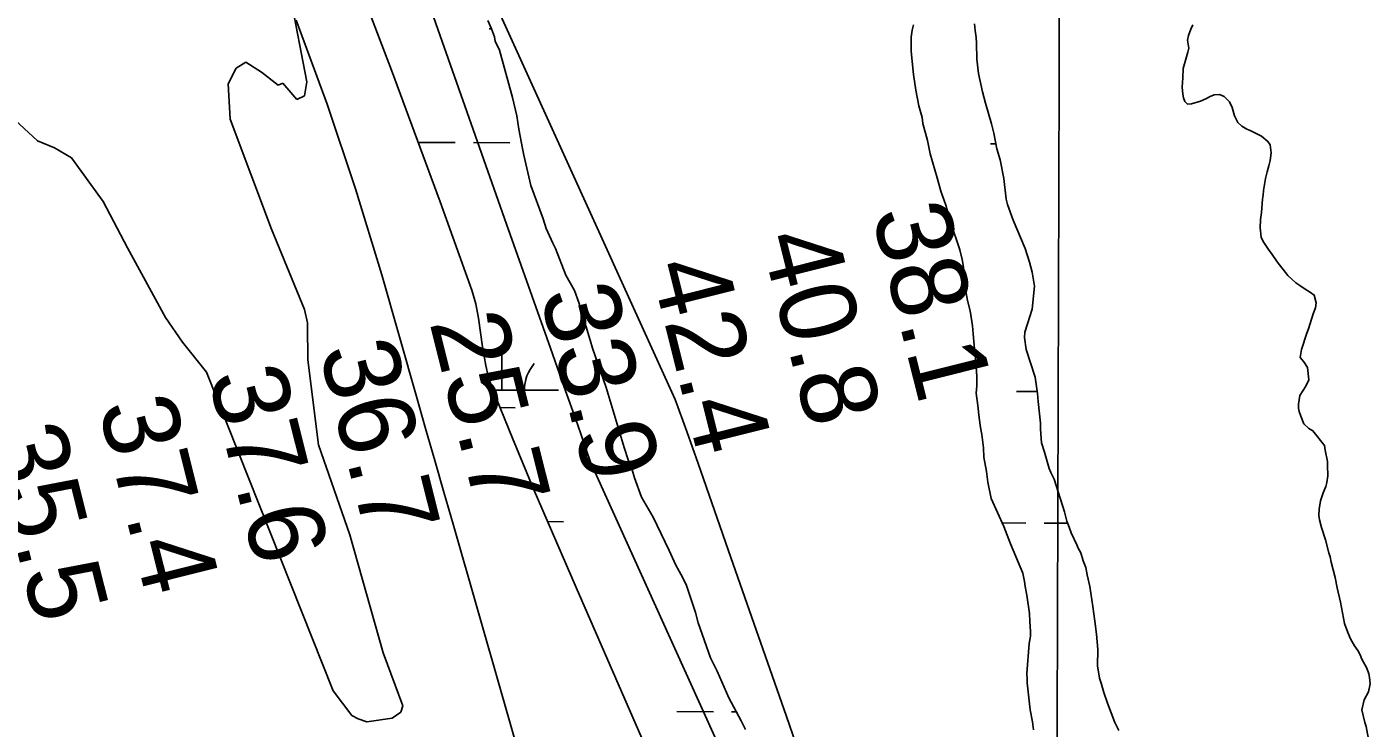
# Model space of a CAD drawing. Extents: x 3161665 to 3199565, y 885729 to 911164.
# Drawn here: x 3180653 to 3181832, y 892545 to 893161 of the extents above; entities that cross this region are included whole.
import ezdxf

# ---------------------------------------------------------------- set-up
doc = ezdxf.new("R2010")
doc.units = 0
for name, color, linetype in [('V-GRID-MAJR', 7, 'Continuous'), ('V-RIVR-RANG', 7, 'Continuous'), ('V-SITE-VEGE', 7, 'Continuous'), ('V-TOPO-MAJR', 7, 'Continuous'), ('V-TOPO-MINR', 7, 'Continuous'), ('V-TOPO-SHOR', 7, 'Continuous'), ('V-WETL-SWMP', 7, 'Continuous')]:
    doc.layers.add(name, color=color, linetype=linetype)

msp = doc.modelspace()

# ---------------------------------------------------------------- linework, layer by layer
at = {"layer": 'V-GRID-MAJR'}
msp.add_spline([(3181553.2, 891152.2), (3181570, 897211.5), (3181586.7, 903274.3), (3181603.5, 909337.1), (3181603.5, 909340.5)], degree=3, dxfattribs=at)
at = {"layer": 'V-SITE-VEGE'}
for p, q in [((3180898.3, 893112.3), (3180848.3, 893374.1)), ((3180928.8, 893237.8), (3180972.7, 893122.6)), ((3181485.2, 893157.4), (3181484.7, 893163.4)), ((3181486.1, 893151.4), (3181485.2, 893157.4)), ((3181674.5, 893158.7), (3181672.4, 893153)), ((3181676.4, 893162.3), (3181674.5, 893158.7)), ((3181486.3, 893146.3), (3181486.1, 893151.4)), ((3181486.5, 893132.2), (3181486.3, 893146.3)), ((3181672.4, 893153), (3181671.5, 893149.1)), ((3181671.5, 893149.1), (3181672.9, 893141.9)), ((3181488.2, 893119.6), (3181486.5, 893132.2)), ((3181672, 893138.3), (3181667.7, 893124)), ((3181672.9, 893141.9), (3181672, 893138.3)), ((3180829.4, 893110.6), (3180836.3, 893124.4)), ((3180836.3, 893124.4), (3180844.9, 893129.5)), ((3180844.9, 893129.5), (3180858.6, 893120.9)), ((3180858.6, 893120.9), (3180873.3, 893109.5)), ((3180972.7, 893122.6), (3181015.4, 893006.9)), ((3181491.7, 893103.7), (3181488.2, 893119.6)), ((3181667.7, 893124), (3181667.6, 893115.9)), ((3180831.1, 893079.6), (3180829.4, 893110.6)), ((3180873.3, 893109.5), (3180877.4, 893111.2)), ((3180877.4, 893111.2), (3180889.6, 893096.8)), ((3180896.5, 893100.2), (3180898.3, 893112.3)), ((3181667.6, 893115.9), (3181667, 893107.8)), ((3181667, 893107.8), (3181667.5, 893101.5)), ((3180889.6, 893096.8), (3180896.5, 893100.2)), ((3181494.3, 893093.5), (3181491.7, 893103.7)), ((3181667.5, 893101.5), (3181668.1, 893098.2)), ((3181668.1, 893098.2), (3181669.3, 893095.1)), ((3181683.1, 893095.3), (3181687.6, 893097.4)), ((3181687.6, 893097.4), (3181691.5, 893099.5)), ((3181691.5, 893099.5), (3181695.1, 893101)), ((3181695.1, 893101), (3181699.6, 893101.2)), ((3181699.6, 893101.2), (3181703.8, 893099.4)), ((3181703.8, 893099.4), (3181708.6, 893094.9)), ((3181499.6, 893075.4), (3181494.3, 893093.5)), ((3181669.3, 893095.1), (3181671.6, 893092.7)), ((3181671.6, 893092.7), (3181675.2, 893093)), ((3181675.2, 893093), (3181683.1, 893095.3)), ((3181708.6, 893094.9), (3181710.9, 893089.7)), ((3181710.9, 893089.7), (3181713, 893082.5)), ((3180638.5, 893082.1), (3180662, 893060.7)), ((3180867.3, 892983.1), (3180831.1, 893079.6)), ((3181501.6, 893067.3), (3181499.6, 893075.4)), ((3181713, 893082.5), (3181715.9, 893076.8)), ((3181715.9, 893076.8), (3181719.2, 893073.5)), ((3181719.2, 893073.5), (3181723.7, 893070.7)), ((3180662, 893060.7), (3180677, 893054.3)), ((3181504.2, 893053.5), (3181501.6, 893067.3)), ((3181723.7, 893070.7), (3181726.7, 893069.5)), ((3181726.7, 893069.5), (3181736.5, 893064.6)), ((3181736.5, 893064.6), (3181742.2, 893060.1)), ((3180677, 893054.3), (3180691.9, 893045.7)), ((3181507.2, 893043.9), (3181504.2, 893053.5)), ((3181742.2, 893060.1), (3181744.3, 893057.1)), ((3181745.1, 893049.9), (3181744.2, 893043.3)), ((3181744.3, 893057.1), (3181745.1, 893049.9)), ((3180691.9, 893045.7), (3180719.7, 893007.2)), ((3181510.4, 893027.6), (3181507.2, 893043.9)), ((3181742.9, 893038.5), (3181741.4, 893033.4)), ((3181744.2, 893043.3), (3181742.9, 893038.5)), ((3181512.3, 893009.3), (3181510.4, 893027.6)), ((3181740.1, 893027.4), (3181738.3, 893016.9)), ((3181741.4, 893033.4), (3181740.1, 893027.4)), ((3181738.3, 893016.9), (3181737.9, 893013)), ((3180719.7, 893007.2), (3180741.1, 892966.6)), ((3181015.4, 893006.9), (3181043.2, 892929.5)), ((3181513.5, 893004.8), (3181512.3, 893009.3)), ((3181518.5, 892991), (3181513.5, 893004.8)), ((3181737.3, 893009.4), (3181736.6, 892997.7)), ((3181737.9, 893013), (3181737.3, 893009.4)), ((3181529.1, 892966), (3181518.5, 892991)), ((3181735.7, 892991.4), (3181735.3, 892984.3)), ((3181736.6, 892997.7), (3181735.7, 892991.4)), ((3180896.5, 892912.5), (3180867.3, 892983.1)), ((3181735.3, 892984.3), (3181736.2, 892976.1)), ((3180741.1, 892966.6), (3180774.3, 892905.6)), ((3181736.2, 892976.1), (3181737.9, 892972.2)), ((3181737.9, 892972.2), (3181743.3, 892964.4)), ((3181532.9, 892954), (3181529.1, 892966)), ((3181743.3, 892964.4), (3181745.4, 892961.7)), ((3181745.4, 892961.7), (3181750.4, 892954.4)), ((3181750.4, 892954.4), (3181759.6, 892942.4)), ((3181535.2, 892945.2), (3181532.9, 892954)), ((3181537.2, 892932.9), (3181535.2, 892945.2)), ((3181535.3, 892912.8), (3181537.2, 892932.9)), ((3181759.6, 892942.4), (3181766.8, 892936)), ((3181766.8, 892936), (3181770.3, 892933.6)), ((3181770.3, 892933.6), (3181773.9, 892930.9)), ((3181773.9, 892930.9), (3181779.6, 892927.5)), ((3181043.2, 892929.5), (3181046.7, 892917.4)), ((3181779.6, 892927.5), (3181782.9, 892925.1)), ((3181782.9, 892925.1), (3181784.6, 892918.2)), ((3180899, 892900.8), (3180896.5, 892912.5)), ((3181046.7, 892917.4), (3181049.2, 892905)), ((3181531, 892900), (3181535.3, 892912.8)), ((3181781.9, 892908.6), (3181777.9, 892895.4)), ((3181784, 892914), (3181781.9, 892908.6)), ((3181784.6, 892918.2), (3181784, 892914)), ((3180774.3, 892905.6), (3180789.1, 892883.8)), ((3180899.1, 892898.5), (3180899, 892900.8)), ((3180899.2, 892868.3), (3180899.1, 892898.5)), ((3181049.2, 892905), (3181052.7, 892879.8)), ((3181528.8, 892892.5), (3181531, 892900)), ((3181777.9, 892895.4), (3181776.3, 892891.8)), ((3180789.1, 892883.8), (3180810.4, 892857.4)), ((3181528.5, 892888), (3181528.8, 892892.5)), ((3181529.9, 892877.5), (3181528.5, 892888)), ((3181776.3, 892891.8), (3181771.7, 892877.5)), ((3181052.7, 892879.8), (3181055.5, 892863.2)), ((3181537.8, 892853.1), (3181529.9, 892877.5)), ((3181771.7, 892877.5), (3181770.5, 892870.3)), ((3180908.6, 892793.7), (3180899.2, 892868.3)), ((3181055.5, 892863.2), (3181057.7, 892853.8)), ((3181770.5, 892870.3), (3181773.7, 892866.4)), ((3181773.7, 892866.4), (3181777, 892861.5)), ((3181777, 892861.5), (3181778.1, 892850.7)), ((3180810.4, 892857.4), (3180921.6, 892577.6)), ((3181057.7, 892853.8), (3181061.2, 892843.5)), ((3181539.8, 892838.7), (3181537.8, 892853.1)), ((3181778.1, 892850.7), (3181775.4, 892845.1)), ((3181061.2, 892843.5), (3181078.9, 892799.4)), ((3181540.4, 892831.8), (3181539.8, 892838.7)), ((3181770.2, 892837), (3181769, 892829.5)), ((3181775.4, 892845.1), (3181770.2, 892837)), ((3181542.6, 892812.6), (3181540.4, 892831.8)), ((3181769, 892829.5), (3181768.9, 892825.9)), ((3181768.9, 892825.9), (3181769.5, 892822.9)), ((3181769.5, 892822.9), (3181771, 892818.7)), ((3181771, 892818.7), (3181773.6, 892812.1)), ((3181542.6, 892807.5), (3181542.6, 892812.6)), ((3181543.4, 892795.5), (3181542.6, 892807.5)), ((3181773.6, 892812.1), (3181778.1, 892808.1)), ((3181778.1, 892808.1), (3181781.7, 892806)), ((3181781.7, 892806), (3181791.8, 892793)), ((3180936.1, 892714.5), (3180908.6, 892793.7)), ((3181078.9, 892799.4), (3181097.2, 892755.5)), ((3181546.1, 892787.1), (3181543.4, 892795.5)), ((3181791.8, 892793), (3181792.4, 892789.1)), ((3181792.4, 892789.1), (3181794.4, 892778.9)), ((3181550.1, 892772.9), (3181546.1, 892787.1)), ((3181794.4, 892778.9), (3181794.4, 892775.6)), ((3181551.6, 892769.3), (3181550.1, 892772.9)), ((3181554.6, 892763.6), (3181551.6, 892769.3)), ((3181794.9, 892766.3), (3181794, 892760.6)), ((3181794.4, 892775.6), (3181794.9, 892766.3)), ((3181097.2, 892755.5), (3181134.8, 892668.3)), ((3181563.7, 892734.7), (3181554.6, 892763.6)), ((3181793, 892757), (3181790.6, 892751.6)), ((3181794, 892760.6), (3181793, 892757)), ((3181788.4, 892744.5), (3181787.2, 892737.3)), ((3181789.4, 892748.1), (3181788.4, 892744.5)), ((3181790.6, 892751.6), (3181789.4, 892748.1)), ((3181565.7, 892726.6), (3181563.7, 892734.7)), ((3181787.2, 892737.3), (3181786.8, 892731.6)), ((3181786.8, 892731.6), (3181787.4, 892727.7)), ((3181567.8, 892721.5), (3181565.7, 892726.6)), ((3181569.5, 892716.4), (3181567.8, 892721.5)), ((3181787.4, 892727.7), (3181789.2, 892721.1)), ((3181789.2, 892721.1), (3181792.7, 892710.2)), ((3180965.4, 892611.1), (3180936.1, 892714.5)), ((3181574.5, 892705.9), (3181569.5, 892716.4)), ((3181792.7, 892710.2), (3181795.6, 892698.8)), ((3181575.7, 892702.8), (3181574.5, 892705.9)), ((3181577.8, 892698.9), (3181575.7, 892702.8)), ((3181580.1, 892691.7), (3181577.8, 892698.9)), ((3181795.6, 892698.8), (3181796.8, 892695.2)), ((3181796.8, 892695.2), (3181797.6, 892690.7)), ((3181582.2, 892686), (3181580.1, 892691.7)), ((3181583.4, 892679.4), (3181582.2, 892686)), ((3181797.6, 892690.7), (3181801.1, 892677.2)), ((3181585.7, 892669.2), (3181583.4, 892679.4)), ((3181801.1, 892677.2), (3181802.9, 892668.2)), ((3181134.8, 892668.3), (3181164.7, 892599.9)), ((3181588.5, 892651.8), (3181585.7, 892669.2)), ((3181802.9, 892668.2), (3181805.8, 892655.5)), ((3181590.2, 892638.8), (3181588.5, 892651.8)), ((3181805.8, 892655.5), (3181809.5, 892636.9)), ((3181591.7, 892627.4), (3181590.2, 892638.8)), ((3181809.5, 892636.9), (3181812.5, 892628.8)), ((3181592.8, 892613.9), (3181591.7, 892627.4)), ((3181812.5, 892628.8), (3181814.8, 892623.4)), ((3181592.7, 892599.5), (3181592.8, 892613.9)), ((3181814.8, 892623.4), (3181818.1, 892617.3)), ((3181818.1, 892617.3), (3181821.1, 892613.1)), ((3181821.1, 892613.1), (3181823.1, 892609.2)), ((3180982.6, 892564.6), (3180965.4, 892611.1)), ((3181823.1, 892609.2), (3181824.6, 892605.6)), ((3181824.6, 892605.6), (3181829, 892597.5)), ((3181164.7, 892599.9), (3181194.7, 892531.5)), ((3181594.4, 892588.7), (3181592.7, 892599.5)), ((3181595.8, 892584.5), (3181594.4, 892588.7)), ((3181829, 892597.5), (3181830.8, 892592.6)), ((3181830.8, 892592.6), (3181831.4, 892589.3)), ((3181831.4, 892589.3), (3181831.9, 892583.9)), ((3180921.6, 892577.6), (3180937.9, 892556)), ((3181598.2, 892576.1), (3181595.8, 892584.5)), ((3181831.9, 892583.9), (3181830.4, 892576.7)), ((3181601.4, 892566.8), (3181598.2, 892576.1)), ((3181607.9, 892549.9), (3181601.4, 892566.8)), ((3181826.7, 892569.9), (3181824.6, 892560.9)), ((3181830.4, 892576.7), (3181826.7, 892569.9)), ((3180937.9, 892556), (3180943.5, 892553.1)), ((3180951, 892550.4), (3180973.4, 892553.6)), ((3180973.4, 892553.6), (3180980.9, 892558.9)), ((3180980.9, 892558.9), (3180982.6, 892564.6)), ((3181824.6, 892560.9), (3181827.2, 892549.8)), ((3180943.5, 892553.1), (3180951, 892550.4)), ((3181611.4, 892542.7), (3181607.9, 892549.9)), ((3181827.2, 892549.8), (3181828.4, 892546.2)), ((3181828.4, 892546.2), (3181831.2, 892532))]:
    msp.add_line(p, q, dxfattribs=at)
at = {"layer": 'V-TOPO-MAJR'}
msp.add_lwpolyline([(3181343.1, 892486.4), (3181319.1, 892555.9), (3181294.9, 892625.4), (3181270.7, 892694.8), (3181241.9, 892777.2), (3181232, 892805.4), (3181221.9, 892833.5), (3181001.3, 893318.7), (3180984.3, 893358.2), (3180968.7, 893398.2), (3180954.2, 893438.7), (3180916.7, 893549), (3180909.8, 893569.5), (3180903, 893590.1), (3180896.3, 893610.7), (3180889.7, 893631.4), (3180849, 893761.2), (3180822.7, 893847)], dxfattribs=at)
at = {"layer": 'V-TOPO-MINR'}
for points in [[(3181395.1, 892231.3), (3181147.5, 892778.3), (3181135.9, 892811.7), (3181124.1, 892845.2), (3181112.3, 892878.6), (3181073.7, 892987.5), (3181042.6, 893075.5), (3181011.8, 893163.5), (3180981.3, 893251.6), (3180951, 893339.7), (3180888.6, 893522.5), (3180878.3, 893552.8), (3180868.2, 893583.2), (3180858.2, 893613.6), (3180848.3, 893644.1), (3180838.3, 893674.5), (3180828.2, 893704.9), (3180817.7, 893735.2), (3180807.1, 893765.4), (3180759.8, 893897.1)], [(3180888.9, 893166.5), (3180916.4, 893092.9), (3180941.2, 893018.3), (3180964.2, 892943), (3180994.7, 892836.2), (3181002.7, 892808.1), (3181010.7, 892780), (3181018.7, 892752), (3181026.8, 892723.9), (3181177.7, 892197.5)]]:
    msp.add_lwpolyline(points, dxfattribs=at)
at = {"layer": 'V-TOPO-SHOR'}
for points in [[(3181484.7, 893163.4), (3181485.2, 893157.4), (3181486.1, 893151.4), (3181486.3, 893146.3), (3181486.5, 893132.2), (3181488.2, 893119.6), (3181491.7, 893103.7), (3181494.3, 893093.5), (3181499.6, 893075.4), (3181501.6, 893067.3), (3181504.2, 893053.5), (3181507.2, 893043.9), (3181510.4, 893027.6), (3181512.3, 893009.3), (3181513.5, 893004.8), (3181518.5, 892991), (3181529.1, 892966), (3181532.9, 892954), (3181535.2, 892945.2), (3181537.2, 892932.9), (3181535.3, 892912.8), (3181531, 892900), (3181528.8, 892892.5), (3181528.5, 892888), (3181529.9, 892877.5), (3181537.8, 892853.1), (3181539.8, 892838.7), (3181540.4, 892831.8), (3181542.6, 892812.6), (3181542.6, 892807.5), (3181543.4, 892795.5), (3181546.1, 892787.1), (3181550.1, 892772.9), (3181551.6, 892769.3), (3181554.6, 892763.6), (3181563.7, 892734.7)], [(3181676.4, 893162.3), (3181674.5, 893158.7), (3181672.4, 893153), (3181671.5, 893149.1), (3181672.9, 893141.9), (3181672, 893138.3), (3181667.7, 893124), (3181667.6, 893115.9), (3181667, 893107.8), (3181667.5, 893101.5), (3181668.1, 893098.2), (3181669.3, 893095.1), (3181671.6, 893092.7), (3181675.2, 893093), (3181683.1, 893095.3), (3181687.6, 893097.4), (3181691.5, 893099.5), (3181695.1, 893101), (3181699.6, 893101.2), (3181703.8, 893099.4), (3181708.6, 893094.9), (3181710.9, 893089.7), (3181713, 893082.5), (3181715.9, 893076.8), (3181719.2, 893073.5), (3181723.7, 893070.7), (3181726.7, 893069.5), (3181736.5, 893064.6), (3181742.2, 893060.1), (3181744.3, 893057.1), (3181745.1, 893049.9), (3181744.2, 893043.3), (3181742.9, 893038.5), (3181741.4, 893033.4), (3181740.1, 893027.4), (3181738.3, 893016.9), (3181737.9, 893013), (3181737.3, 893009.4), (3181736.6, 892997.7), (3181735.7, 892991.4), (3181735.3, 892984.3), (3181736.2, 892976.1), (3181737.9, 892972.2), (3181743.3, 892964.4), (3181745.4, 892961.7), (3181750.4, 892954.4), (3181759.6, 892942.4), (3181766.8, 892936), (3181770.3, 892933.6), (3181773.9, 892930.9), (3181779.6, 892927.5), (3181782.9, 892925.1), (3181784.6, 892918.2), (3181784, 892914), (3181781.9, 892908.6), (3181777.9, 892895.4), (3181776.3, 892891.8), (3181771.7, 892877.5), (3181770.5, 892870.3), (3181773.7, 892866.4), (3181777, 892861.5), (3181778.1, 892850.7), (3181775.4, 892845.1), (3181770.2, 892837), (3181769, 892829.5), (3181768.9, 892825.9), (3181769.5, 892822.9), (3181771, 892818.7), (3181773.6, 892812.1)], [(3181773.6, 892812.1), (3181778.1, 892808.1), (3181781.7, 892806), (3181791.8, 892793), (3181792.4, 892789.1), (3181794.4, 892778.9), (3181794.4, 892775.6), (3181794.9, 892766.3), (3181794, 892760.6), (3181793, 892757), (3181790.6, 892751.6), (3181789.4, 892748.1), (3181788.4, 892744.5), (3181787.2, 892737.3), (3181786.8, 892731.6), (3181787.4, 892727.7), (3181789.2, 892721.1), (3181792.7, 892710.2), (3181795.6, 892698.8), (3181796.8, 892695.2), (3181797.6, 892690.7), (3181801.1, 892677.2), (3181802.9, 892668.2), (3181805.8, 892655.5), (3181809.5, 892636.9), (3181812.5, 892628.8), (3181814.8, 892623.4), (3181818.1, 892617.3), (3181821.1, 892613.1), (3181823.1, 892609.2), (3181824.6, 892605.6), (3181829, 892597.5), (3181830.8, 892592.6), (3181831.4, 892589.3), (3181831.9, 892583.9), (3181830.4, 892576.7), (3181826.7, 892569.9), (3181824.6, 892560.9), (3181827.2, 892549.8), (3181828.4, 892546.2), (3181831.2, 892532)], [(3181563.7, 892734.7), (3181565.7, 892726.6), (3181567.8, 892721.5), (3181569.5, 892716.4), (3181574.5, 892705.9), (3181575.7, 892702.8), (3181577.8, 892698.9), (3181580.1, 892691.7), (3181582.2, 892686), (3181583.4, 892679.4), (3181585.7, 892669.2), (3181588.5, 892651.8), (3181590.2, 892638.8), (3181591.7, 892627.4), (3181592.8, 892613.9), (3181592.7, 892599.5), (3181594.4, 892588.7), (3181595.8, 892584.5), (3181598.2, 892576.1), (3181601.4, 892566.8), (3181607.9, 892549.9), (3181611.4, 892542.7)]]:
    msp.add_lwpolyline(points, dxfattribs=at)
at = {"layer": 'V-WETL-SWMP'}
for p, q in [((3181058.4, 893159), (3181060.6, 893159)), ((3180996.7, 893059.2), (3181028.7, 893059.1)), ((3181044.7, 893059), (3181076.7, 893058.9)), ((3181498.6, 893057.8), (3181503.4, 893057.8)), ((3181069.5, 892841.7), (3181069.6, 892877.7)), ((3181061.9, 892841.7), (3181119.5, 892841.6)), ((3181521.4, 892840.5), (3181539.6, 892840.4)), ((3181068.1, 892826.3), (3181081.4, 892826.2)), ((3181109.8, 892726.2), (3181123.7, 892726.1)), ((3181508.8, 892725.1), (3181529.7, 892725)), ((3181545.7, 892725), (3181566.4, 892724.9)), ((3181223.3, 892559.4), (3181255.3, 892559.3)), ((3181271.3, 892559.2), (3181275.4, 892559.2))]:
    msp.add_line(p, q, dxfattribs=at)
for points in [[(3181194.7, 892531.5), (3181164.7, 892599.9), (3181134.8, 892668.3), (3181097.2, 892755.5), (3181078.9, 892799.4), (3181061.2, 892843.5), (3181057.7, 892853.8), (3181055.5, 892863.2), (3181052.7, 892879.8), (3181049.2, 892905), (3181046.7, 892917.4), (3181043.2, 892929.5), (3181015.4, 893006.9), (3180972.7, 893122.6), (3180928.8, 893237.8), (3180901.1, 893308.3), (3180892.3, 893332.8), (3180880.4, 893370.1), (3180869.5, 893407.7), (3180865.9, 893421.4)], [(3181057.4, 893166.2), (3181060.6, 893159), (3181063.1, 893151.9), (3181063.7, 893148), (3181067.6, 893140.2), (3181078.9, 893098.6), (3181082.7, 893082.4), (3181084.5, 893070.7), (3181087.7, 893053.8), (3181088.9, 893048), (3181095.2, 893021.4), (3181106, 892992.1), (3181108.5, 892983.7), (3181114.3, 892970.7), (3181116.8, 892966.1), (3181125.7, 892942.7), (3181133.4, 892929.1), (3181137.2, 892918.7), (3181147.3, 892885.5), (3181149.2, 892878.4), (3181161.3, 892843.9), (3181177.1, 892791.3), (3181180.9, 892779.6), (3181184.1, 892771.8), (3181186, 892764.7), (3181192.3, 892747.8), (3181202.5, 892730.2), (3181216.6, 892701), (3181222.3, 892688), (3181226.8, 892680.1), (3181231.3, 892671), (3181239.5, 892646.3), (3181242, 892637.3), (3181252.8, 892606.7), (3181258.6, 892595), (3181268.8, 892571.6), (3181279.6, 892551.4), (3181283.5, 892543.6)], [(3181487.6, 892828.3), (3181486.1, 892839.1), (3181486.5, 892845.4), (3181486.6, 892853.8), (3181485.5, 892869.7), (3181484.9, 892874.5), (3181483.5, 892891), (3181482.7, 892898.2), (3181480.7, 892911.2), (3181478.4, 892920.5), (3181476.9, 892928.6), (3181475.5, 892940.3), (3181475, 892949.6), (3181473.8, 892956.5), (3181471.8, 892964.9), (3181463.3, 892989.9), (3181459.5, 893004), (3181455.1, 893016.3), (3181451.9, 893028.1), (3181445.7, 893049.1), (3181443.4, 893060.8), (3181439.3, 893075.9), (3181438.5, 893081), (3181435.8, 893091.2), (3181433.2, 893105), (3181430.9, 893118.8), (3181429.5, 893133.2), (3181429, 893139.5), (3181429.1, 893151.5), (3181430, 893157.8), (3181431, 893162.3)], [(3181484.7, 893163.4), (3181485.2, 893157.4), (3181486.1, 893151.4), (3181486.3, 893146.3), (3181486.5, 893132.2), (3181488.2, 893119.6), (3181491.7, 893103.7), (3181494.3, 893093.5), (3181499.6, 893075.4), (3181501.6, 893067.3), (3181504.2, 893053.5), (3181507.2, 893043.9), (3181510.4, 893027.6), (3181512.3, 893009.3), (3181513.5, 893004.8), (3181518.5, 892991), (3181529.1, 892966), (3181532.9, 892954), (3181535.2, 892945.2), (3181537.2, 892932.9), (3181535.3, 892912.8), (3181531, 892900), (3181528.8, 892892.5), (3181528.5, 892888), (3181529.9, 892877.5), (3181537.8, 892853.1), (3181539.8, 892838.7), (3181540.4, 892831.8), (3181542.6, 892812.6), (3181542.6, 892807.5), (3181543.4, 892795.5), (3181546.1, 892787.1), (3181550.1, 892772.9), (3181551.6, 892769.3), (3181554.6, 892763.6), (3181563.7, 892734.7)], [(3181536.4, 892543.5), (3181535.6, 892550.4), (3181533.6, 892561), (3181530.7, 892584.7), (3181530.8, 892588), (3181530.5, 892592.8), (3181532.5, 892619.2), (3181533.7, 892625.8), (3181533.8, 892629.7), (3181533.2, 892638.4), (3181533, 892645.6), (3181530.4, 892661.8), (3181529, 892669.3), (3181528.4, 892673.8), (3181527, 892681), (3181516.1, 892706.6), (3181510.2, 892721.9), (3181499.3, 892746.6), (3181496.4, 892761), (3181495.2, 892770.3), (3181492.9, 892782.7), (3181492.4, 892791.1), (3181491, 892802.8), (3181489.8, 892808.8), (3181488.7, 892817.5), (3181487.6, 892828.3)], [(3181563.7, 892734.7), (3181565.7, 892726.6), (3181567.8, 892721.5), (3181569.5, 892716.4), (3181574.5, 892705.9), (3181575.7, 892702.8), (3181577.8, 892698.9), (3181580.1, 892691.7), (3181582.2, 892686), (3181583.4, 892679.4), (3181585.7, 892669.2), (3181588.5, 892651.8), (3181590.2, 892638.8), (3181591.7, 892627.4), (3181592.8, 892613.9), (3181592.7, 892599.5), (3181594.4, 892588.7), (3181595.8, 892584.5), (3181598.2, 892576.1), (3181601.4, 892566.8), (3181607.9, 892549.9), (3181611.4, 892542.7)]]:
    msp.add_lwpolyline(points, dxfattribs=at)
msp.add_arc((3181124.7, 892842), 35.2, 139.0698, 180.6135, dxfattribs=at)

# ---------------------------------------------------------------- texts
at = {"layer": 'V-RIVR-RANG'}
for s, p in [('38.1', (3181394.2, 892997.3)), ('40.8', (3181296.7, 892975.1)), ('42.4', (3181199.8, 892950.5)), ('33.9', (3181102.8, 892926.2)), ('25.7', (3181005.9, 892901.4)), ('36.7', (3180909, 892876.8)), ('37.6', (3180811.6, 892854)), ('37.4', (3180715.1, 892827.6)), ('35.5', (3180618.2, 892803.1))]:
    msp.add_text(s, height=67, rotation=284.0783, dxfattribs=at).set_placement(p)

doc.saveas('drawing.dxf')
